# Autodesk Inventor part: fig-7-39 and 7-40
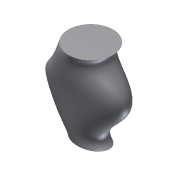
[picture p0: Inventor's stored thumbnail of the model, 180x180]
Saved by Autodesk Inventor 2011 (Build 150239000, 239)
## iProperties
Shininess: 64.0
Length Units: 11269
Angle Units: 11279
Time Units: 11290
Mass Units: 11283
Length Display Precision: 3
Angle Display Precision: 2
Compacted: True
Part Number: fig-7-39 and 7-40
Document SubType Name: Modeling
Created: 2002-12
Designer: deepak
Density: 1 g/cm^3
Density: 0.0
Volumn: 0.0
Area: 0.0
PropertySet Name: Model Information
Control State: 0
Master: False
Checked Out: False
Author: deepak
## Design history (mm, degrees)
sketch "Sketch1"
  geometry: 2 further points; 1 other entity
  constraints: 1 coincident, 3 other
workplane "Work Plane1"
workplane "Work Plane2"
sketch "Sketch3"
  geometry: C1 r 60 at (0, 0); 1 further point
  constraints: 1 centre point, 1 coincident, 1 other
sketch "Sketch4"
  geometry: 8 further points
  constraints: 8 other
sketch "Sketch5"
  geometry: 6 further points
  constraints: 6 other
sketch "Sketch6"
  geometry: 6 further points
  constraints: 6 other
  dimensions: "d20" = 35 distance of point (0, 0) point (-35, 0); "d21" = 0 vertical distance of point (0, 0) point (-35, 0); "d22" = 225 vertical distance of point (0, 0) point (-60, 225); "d23" = 60 horizontal distance of point (0, 0) point (-60, 225); "d24" = 100 horizontal distance of point (0, 0) point (-100, 125); "d25" = 125 vertical distance of point (0, 0) point (-100, 125)
loft "Loft3" dims "d42" = 0, "d43" = 90 deg, "d44" = 0, "d45" = 90 deg, "d46" = 0, "d47" = 90 deg, "d48" = 0, "d49" = 90 deg
node "Sketch7"
body "Solid1"
other parameters: "d5" = 125
